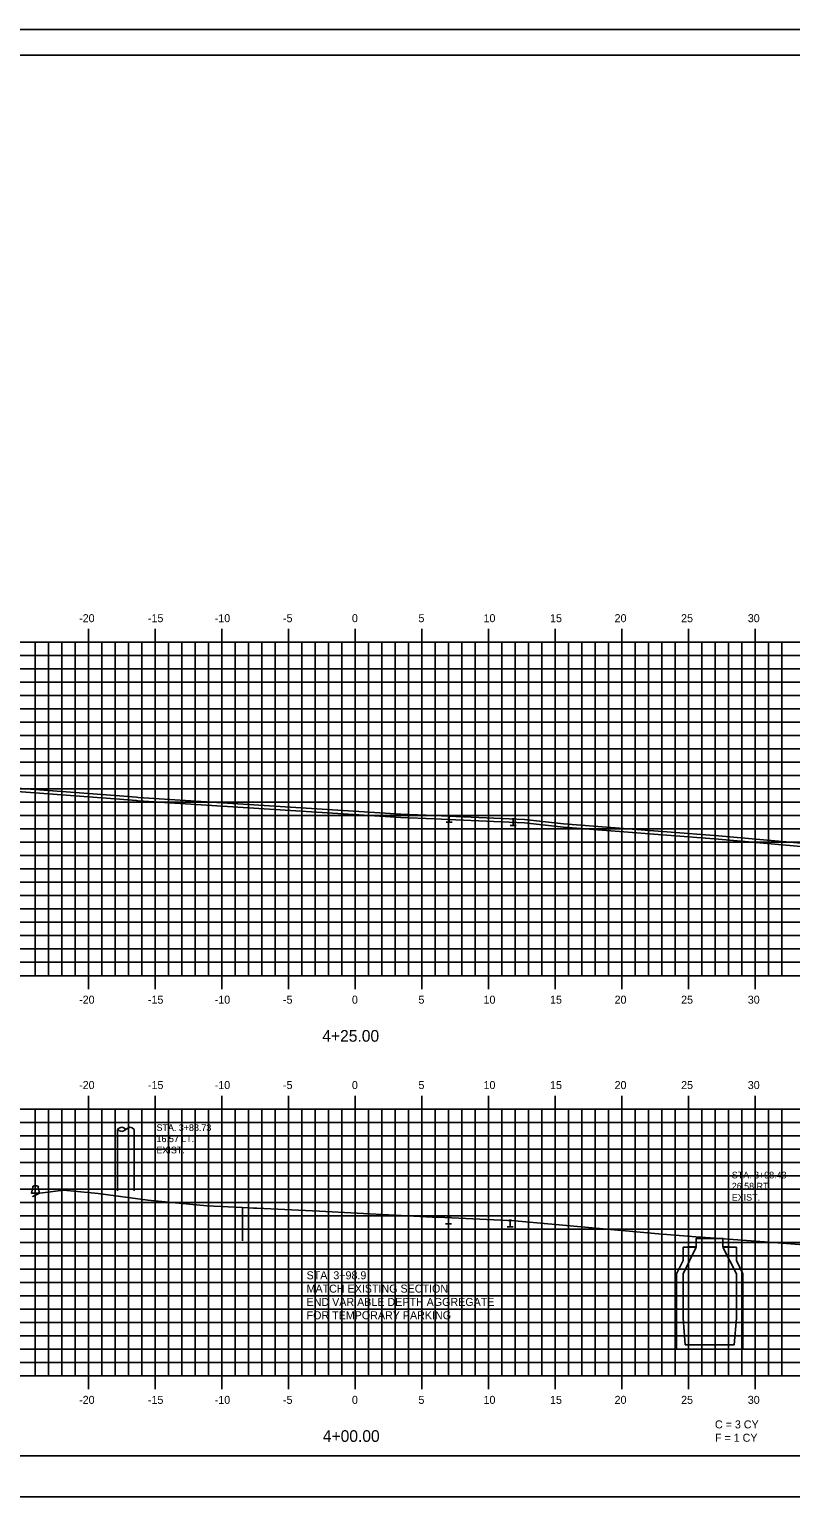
# Model space of a CAD drawing. Extents: x 1026213 to 1026383, y 394615 to 394725.
# Drawn here: x 1026272 to 1026329.1, y 394614.9 to 394724.9 of the extents above; entities that cross this region are included whole.
import ezdxf

# ---------------------------------------------------------------- set-up
doc = ezdxf.new("R2010")
doc.units = 0
for name, color, linetype in [('ANNOTATION', 7, 'Continuous'), ('BORDER', 7, 'Continuous'), ('D_Roadway_Centerline', 7, 'Continuous'), ('D_Roadway_SlopeLines', 7, 'Continuous'), ('D_Text_Monospaced', 7, 'Continuous'), ('H_V ANNOTATION', 7, 'Continuous'), ('MAJOR', 7, 'Continuous'), ('MINOR', 7, 'Continuous'), ('PLOT BOUNDARY', 7, 'Continuous'), ('S_Curb_Type_3', 7, 'Continuous'), ('S_Drainage_CB', 7, 'Continuous'), ('S_Railroad_Tracks', 7, 'Continuous'), ('S_Roadway_Centerline', 7, 'Continuous'), ('S_Roadway_Edge_Pavement', 7, 'Continuous'), ('S_Utilities_Pole_Power', 7, 'Continuous')]:
    doc.layers.add(name, color=color, linetype=linetype)

msp = doc.modelspace()

# ---------------------------------------------------------------- linework, layer by layer
at = {"layer": 'BORDER'}
for p, q in [((1026381.43, 394722.93), (1026221.43, 394722.93)), ((1026221.43, 394617.93), (1026381.43, 394617.93))]:
    msp.add_line(p, q, dxfattribs=at)
at = {"layer": 'D_Roadway_SlopeLines'}
msp.add_lwpolyline([(1026296.43, 394636.14), (1026296.43, 394636.14)], dxfattribs=at)
at = {"layer": 'MAJOR'}
for p, q in [((1026226.43, 394678.93), (1026366.43, 394678.93)), ((1026276.43, 394679.93), (1026276.43, 394678.93)), ((1026276.43, 394653.93), (1026276.43, 394678.93)), ((1026281.43, 394679.93), (1026281.43, 394678.93)), ((1026281.43, 394653.93), (1026281.43, 394678.93)), ((1026286.43, 394679.93), (1026286.43, 394678.93)), ((1026286.43, 394653.93), (1026286.43, 394678.93)), ((1026291.43, 394679.93), (1026291.43, 394678.93)), ((1026291.43, 394653.93), (1026291.43, 394678.93)), ((1026296.43, 394679.93), (1026296.43, 394678.93)), ((1026296.43, 394653.93), (1026296.43, 394678.93)), ((1026301.43, 394679.93), (1026301.43, 394678.93)), ((1026301.43, 394653.93), (1026301.43, 394678.93)), ((1026306.43, 394679.93), (1026306.43, 394678.93)), ((1026306.43, 394653.93), (1026306.43, 394678.93)), ((1026311.43, 394679.93), (1026311.43, 394678.93)), ((1026311.43, 394653.93), (1026311.43, 394678.93)), ((1026316.43, 394679.93), (1026316.43, 394678.93)), ((1026316.43, 394653.93), (1026316.43, 394678.93)), ((1026321.43, 394679.93), (1026321.43, 394678.93)), ((1026321.43, 394653.93), (1026321.43, 394678.93)), ((1026326.43, 394679.93), (1026326.43, 394678.93)), ((1026326.43, 394653.93), (1026326.43, 394678.93)), ((1026226.43, 394673.93), (1026366.43, 394673.93)), ((1026226.43, 394668.93), (1026366.43, 394668.93)), ((1026226.43, 394663.93), (1026366.43, 394663.93)), ((1026226.43, 394658.93), (1026366.43, 394658.93)), ((1026226.43, 394653.93), (1026366.43, 394653.93)), ((1026276.43, 394652.93), (1026276.43, 394653.93)), ((1026281.43, 394652.93), (1026281.43, 394653.93)), ((1026286.43, 394652.93), (1026286.43, 394653.93)), ((1026291.43, 394652.93), (1026291.43, 394653.93)), ((1026296.43, 394652.93), (1026296.43, 394653.93)), ((1026301.43, 394652.93), (1026301.43, 394653.93)), ((1026306.43, 394652.93), (1026306.43, 394653.93)), ((1026311.43, 394652.93), (1026311.43, 394653.93)), ((1026316.43, 394652.93), (1026316.43, 394653.93)), ((1026321.43, 394652.93), (1026321.43, 394653.93)), ((1026326.43, 394652.93), (1026326.43, 394653.93)), ((1026276.43, 394644.93), (1026276.43, 394643.93)), ((1026281.43, 394644.93), (1026281.43, 394643.93)), ((1026286.43, 394644.93), (1026286.43, 394643.93)), ((1026291.43, 394644.93), (1026291.43, 394643.93)), ((1026296.43, 394644.93), (1026296.43, 394643.93)), ((1026301.43, 394644.93), (1026301.43, 394643.93)), ((1026306.43, 394644.93), (1026306.43, 394643.93)), ((1026311.43, 394644.93), (1026311.43, 394643.93)), ((1026316.43, 394644.93), (1026316.43, 394643.93)), ((1026321.43, 394644.93), (1026321.43, 394643.93)), ((1026326.43, 394644.93), (1026326.43, 394643.93)), ((1026226.43, 394643.93), (1026366.43, 394643.93)), ((1026276.43, 394623.93), (1026276.43, 394643.93)), ((1026281.43, 394623.93), (1026281.43, 394643.93)), ((1026286.43, 394623.93), (1026286.43, 394643.93)), ((1026291.43, 394623.93), (1026291.43, 394643.93)), ((1026296.43, 394623.93), (1026296.43, 394643.93)), ((1026301.43, 394623.93), (1026301.43, 394643.93)), ((1026306.43, 394623.93), (1026306.43, 394643.93)), ((1026311.43, 394623.93), (1026311.43, 394643.93)), ((1026316.43, 394623.93), (1026316.43, 394643.93)), ((1026321.43, 394623.93), (1026321.43, 394643.93)), ((1026326.43, 394623.93), (1026326.43, 394643.93)), ((1026226.43, 394638.93), (1026366.43, 394638.93)), ((1026226.43, 394633.93), (1026366.43, 394633.93)), ((1026226.43, 394628.93), (1026366.43, 394628.93)), ((1026226.43, 394623.93), (1026366.43, 394623.93)), ((1026276.43, 394622.93), (1026276.43, 394623.93)), ((1026281.43, 394622.93), (1026281.43, 394623.93)), ((1026286.43, 394622.93), (1026286.43, 394623.93)), ((1026291.43, 394622.93), (1026291.43, 394623.93)), ((1026296.43, 394622.93), (1026296.43, 394623.93)), ((1026301.43, 394622.93), (1026301.43, 394623.93)), ((1026306.43, 394622.93), (1026306.43, 394623.93)), ((1026311.43, 394622.93), (1026311.43, 394623.93)), ((1026316.43, 394622.93), (1026316.43, 394623.93)), ((1026321.43, 394622.93), (1026321.43, 394623.93)), ((1026326.43, 394622.93), (1026326.43, 394623.93))]:
    msp.add_line(p, q, dxfattribs=at)
at = {"layer": 'MINOR'}
for p, q in [((1026272.43, 394653.93), (1026272.43, 394678.93)), ((1026273.43, 394653.93), (1026273.43, 394678.93)), ((1026274.43, 394653.93), (1026274.43, 394678.93)), ((1026275.43, 394653.93), (1026275.43, 394678.93)), ((1026277.43, 394653.93), (1026277.43, 394678.93)), ((1026278.43, 394653.93), (1026278.43, 394678.93)), ((1026279.43, 394653.93), (1026279.43, 394678.93)), ((1026280.43, 394653.93), (1026280.43, 394678.93)), ((1026282.43, 394653.93), (1026282.43, 394678.93)), ((1026283.43, 394653.93), (1026283.43, 394678.93)), ((1026284.43, 394653.93), (1026284.43, 394678.93)), ((1026285.43, 394653.93), (1026285.43, 394678.93)), ((1026287.43, 394653.93), (1026287.43, 394678.93)), ((1026288.43, 394653.93), (1026288.43, 394678.93)), ((1026289.43, 394653.93), (1026289.43, 394678.93)), ((1026290.43, 394653.93), (1026290.43, 394678.93)), ((1026292.43, 394653.93), (1026292.43, 394678.93)), ((1026293.43, 394653.93), (1026293.43, 394678.93)), ((1026294.43, 394653.93), (1026294.43, 394678.93)), ((1026295.43, 394653.93), (1026295.43, 394678.93)), ((1026297.43, 394653.93), (1026297.43, 394678.93)), ((1026298.43, 394653.93), (1026298.43, 394678.93)), ((1026299.43, 394653.93), (1026299.43, 394678.93)), ((1026300.43, 394653.93), (1026300.43, 394678.93)), ((1026302.43, 394653.93), (1026302.43, 394678.93)), ((1026303.43, 394653.93), (1026303.43, 394678.93)), ((1026304.43, 394653.93), (1026304.43, 394678.93)), ((1026305.43, 394653.93), (1026305.43, 394678.93)), ((1026307.43, 394653.93), (1026307.43, 394678.93)), ((1026308.43, 394653.93), (1026308.43, 394678.93)), ((1026309.43, 394653.93), (1026309.43, 394678.93)), ((1026310.43, 394653.93), (1026310.43, 394678.93)), ((1026312.43, 394653.93), (1026312.43, 394678.93)), ((1026313.43, 394653.93), (1026313.43, 394678.93)), ((1026314.43, 394653.93), (1026314.43, 394678.93)), ((1026315.43, 394653.93), (1026315.43, 394678.93)), ((1026317.43, 394653.93), (1026317.43, 394678.93)), ((1026318.43, 394653.93), (1026318.43, 394678.93)), ((1026319.43, 394653.93), (1026319.43, 394678.93)), ((1026320.43, 394653.93), (1026320.43, 394678.93)), ((1026322.43, 394653.93), (1026322.43, 394678.93)), ((1026323.43, 394653.93), (1026323.43, 394678.93)), ((1026324.43, 394653.93), (1026324.43, 394678.93)), ((1026325.43, 394653.93), (1026325.43, 394678.93)), ((1026327.43, 394653.93), (1026327.43, 394678.93)), ((1026328.43, 394653.93), (1026328.43, 394678.93)), ((1026226.43, 394677.93), (1026366.43, 394677.93)), ((1026226.43, 394676.93), (1026366.43, 394676.93)), ((1026226.43, 394675.93), (1026366.43, 394675.93)), ((1026226.43, 394674.93), (1026366.43, 394674.93)), ((1026226.43, 394672.93), (1026366.43, 394672.93)), ((1026226.43, 394671.93), (1026366.43, 394671.93)), ((1026226.43, 394670.93), (1026366.43, 394670.93)), ((1026226.43, 394669.93), (1026366.43, 394669.93)), ((1026226.43, 394667.93), (1026366.43, 394667.93)), ((1026226.43, 394666.93), (1026366.43, 394666.93)), ((1026226.43, 394665.93), (1026366.43, 394665.93)), ((1026226.43, 394664.93), (1026366.43, 394664.93)), ((1026226.43, 394662.93), (1026366.43, 394662.93)), ((1026226.43, 394661.93), (1026366.43, 394661.93)), ((1026226.43, 394660.93), (1026366.43, 394660.93)), ((1026226.43, 394659.93), (1026366.43, 394659.93)), ((1026226.43, 394657.93), (1026366.43, 394657.93)), ((1026226.43, 394656.93), (1026366.43, 394656.93)), ((1026226.43, 394655.93), (1026366.43, 394655.93)), ((1026226.43, 394654.93), (1026366.43, 394654.93)), ((1026272.43, 394623.93), (1026272.43, 394643.93)), ((1026273.43, 394623.93), (1026273.43, 394643.93)), ((1026274.43, 394623.93), (1026274.43, 394643.93)), ((1026275.43, 394623.93), (1026275.43, 394643.93)), ((1026277.43, 394623.93), (1026277.43, 394643.93)), ((1026278.43, 394623.93), (1026278.43, 394643.93)), ((1026279.43, 394623.93), (1026279.43, 394643.93)), ((1026280.43, 394623.93), (1026280.43, 394643.93)), ((1026282.43, 394623.93), (1026282.43, 394643.93)), ((1026283.43, 394623.93), (1026283.43, 394643.93)), ((1026284.43, 394623.93), (1026284.43, 394643.93)), ((1026285.43, 394623.93), (1026285.43, 394643.93)), ((1026287.43, 394623.93), (1026287.43, 394643.93)), ((1026288.43, 394623.93), (1026288.43, 394643.93)), ((1026289.43, 394623.93), (1026289.43, 394643.93)), ((1026290.43, 394623.93), (1026290.43, 394643.93)), ((1026292.43, 394623.93), (1026292.43, 394643.93)), ((1026293.43, 394623.93), (1026293.43, 394643.93)), ((1026294.43, 394623.93), (1026294.43, 394643.93)), ((1026295.43, 394623.93), (1026295.43, 394643.93)), ((1026297.43, 394623.93), (1026297.43, 394643.93)), ((1026298.43, 394623.93), (1026298.43, 394643.93)), ((1026299.43, 394623.93), (1026299.43, 394643.93)), ((1026300.43, 394623.93), (1026300.43, 394643.93)), ((1026302.43, 394623.93), (1026302.43, 394643.93)), ((1026303.43, 394623.93), (1026303.43, 394643.93)), ((1026304.43, 394623.93), (1026304.43, 394643.93)), ((1026305.43, 394623.93), (1026305.43, 394643.93)), ((1026307.43, 394623.93), (1026307.43, 394643.93)), ((1026308.43, 394623.93), (1026308.43, 394643.93)), ((1026309.43, 394623.93), (1026309.43, 394643.93)), ((1026310.43, 394623.93), (1026310.43, 394643.93)), ((1026312.43, 394623.93), (1026312.43, 394643.93)), ((1026313.43, 394623.93), (1026313.43, 394643.93)), ((1026314.43, 394623.93), (1026314.43, 394643.93)), ((1026315.43, 394623.93), (1026315.43, 394643.93)), ((1026317.43, 394623.93), (1026317.43, 394643.93)), ((1026318.43, 394623.93), (1026318.43, 394643.93)), ((1026319.43, 394623.93), (1026319.43, 394643.93)), ((1026320.43, 394623.93), (1026320.43, 394643.93)), ((1026322.43, 394623.93), (1026322.43, 394643.93)), ((1026323.43, 394623.93), (1026323.43, 394643.93)), ((1026324.43, 394623.93), (1026324.43, 394643.93)), ((1026325.43, 394623.93), (1026325.43, 394643.93)), ((1026327.43, 394623.93), (1026327.43, 394643.93)), ((1026328.43, 394623.93), (1026328.43, 394643.93)), ((1026226.43, 394642.93), (1026366.43, 394642.93)), ((1026226.43, 394641.93), (1026366.43, 394641.93)), ((1026226.43, 394640.93), (1026366.43, 394640.93)), ((1026226.43, 394639.93), (1026366.43, 394639.93)), ((1026226.43, 394637.93), (1026366.43, 394637.93)), ((1026226.43, 394636.93), (1026366.43, 394636.93)), ((1026226.43, 394635.93), (1026366.43, 394635.93)), ((1026226.43, 394634.93), (1026366.43, 394634.93)), ((1026226.43, 394632.93), (1026366.43, 394632.93)), ((1026226.43, 394631.93), (1026366.43, 394631.93)), ((1026226.43, 394630.93), (1026366.43, 394630.93)), ((1026226.43, 394629.93), (1026366.43, 394629.93)), ((1026226.43, 394627.93), (1026366.43, 394627.93)), ((1026226.43, 394626.93), (1026366.43, 394626.93)), ((1026226.43, 394625.93), (1026366.43, 394625.93)), ((1026226.43, 394624.93), (1026366.43, 394624.93))]:
    msp.add_line(p, q, dxfattribs=at)
at = {"layer": 'PLOT BOUNDARY'}
msp.add_lwpolyline([(1026213.34, 394614.87), (1026383.34, 394614.87), (1026383.34, 394724.87), (1026213.34, 394724.87)], close=True, dxfattribs=at)
at = {"layer": 'S_Curb_Type_3'}
for points in [[(1026272.25, 394638.07), (1026272.15, 394637.63), (1026272.77, 394637.63), (1026272.67, 394638.07)], [(1026272.25, 394638.07), (1026272.15, 394637.63), (1026272.77, 394637.63), (1026272.67, 394638.07)], [(1026272.55, 394638.17), (1026272.37, 394638.17)], [(1026272.55, 394638.17), (1026272.37, 394638.17)]]:
    msp.add_lwpolyline(points, dxfattribs=at)
for centre, start, end in [((1026272.37, 394638.04), 90, 167.0054), ((1026272.37, 394638.04), 90, 167.0054), ((1026272.55, 394638.04), 12.9946, 90), ((1026272.55, 394638.04), 12.9946, 90)]:
    msp.add_arc(centre, 0.125, start, end, dxfattribs=at)
at = {"layer": 'S_Drainage_CB'}
for p, q in [((1026322.01, 394633.57), (1026321.03, 394633.57)), ((1026321.03, 394633.57), (1026321.03, 394632.58)), ((1026321.03, 394631.57), (1026322.01, 394633.57)), ((1026322.01, 394633.57), (1026321.03, 394633.57)), ((1026321.03, 394633.57), (1026321.03, 394632.58)), ((1026321.03, 394631.57), (1026322.01, 394633.57)), ((1026325.03, 394633.57), (1026324.02, 394633.57)), ((1026324.02, 394633.57), (1026325.03, 394631.57)), ((1026325.03, 394633.57), (1026324.02, 394633.57)), ((1026324.02, 394633.57), (1026325.03, 394631.57)), ((1026325.03, 394632.58), (1026325.03, 394633.57)), ((1026325.03, 394632.58), (1026325.03, 394633.57)), ((1026321.03, 394632.58), (1026320.54, 394631.57)), ((1026321.03, 394632.58), (1026320.54, 394631.57)), ((1026325.52, 394631.57), (1026325.03, 394632.58)), ((1026325.52, 394631.57), (1026325.03, 394632.58)), ((1026320.54, 394631.57), (1026320.54, 394625.92)), ((1026320.54, 394631.57), (1026320.54, 394625.92)), ((1026321.03, 394628.25), (1026321.03, 394631.57)), ((1026321.03, 394628.25), (1026321.03, 394631.57)), ((1026325.03, 394631.57), (1026325.03, 394628.25)), ((1026325.03, 394631.57), (1026325.03, 394628.25)), ((1026325.52, 394625.92), (1026325.52, 394631.57)), ((1026325.52, 394625.92), (1026325.52, 394631.57)), ((1026321.19, 394626.25), (1026321.03, 394628.25)), ((1026321.19, 394626.25), (1026321.03, 394628.25)), ((1026325.03, 394628.25), (1026324.87, 394626.25)), ((1026325.03, 394628.25), (1026324.87, 394626.25)), ((1026324.87, 394626.25), (1026321.19, 394626.25)), ((1026324.87, 394626.25), (1026321.19, 394626.25)), ((1026320.54, 394625.92), (1026325.52, 394625.92)), ((1026320.54, 394625.92), (1026325.52, 394625.92))]:
    msp.add_line(p, q, dxfattribs=at)
msp.add_lwpolyline([(1026324.51, 394633.61), (1026324.02, 394633.61), (1026324.02, 394634.23), (1026322.01, 394634.23), (1026322.01, 394633.61), (1026321.52, 394633.61)], dxfattribs=at)
msp.add_lwpolyline([(1026324.51, 394633.61), (1026324.02, 394633.61), (1026324.02, 394634.23), (1026322.01, 394634.23), (1026322.01, 394633.61), (1026321.52, 394633.61)], dxfattribs=at)
at = {"layer": 'S_Railroad_Tracks'}
for p, q in [((1026303.37, 394665.93), (1026303.6, 394665.93)), ((1026303.37, 394665.93), (1026303.6, 394665.93)), ((1026303.48, 394665.93), (1026303.48, 394665.43)), ((1026303.48, 394665.93), (1026303.48, 394665.43)), ((1026303.25, 394665.43), (1026303.71, 394665.43)), ((1026303.25, 394665.43), (1026303.71, 394665.43)), ((1026308.06, 394665.2), (1026308.52, 394665.2)), ((1026308.06, 394665.2), (1026308.52, 394665.2)), ((1026308.18, 394665.7), (1026308.41, 394665.7)), ((1026308.18, 394665.7), (1026308.41, 394665.7)), ((1026308.29, 394665.7), (1026308.29, 394665.2)), ((1026308.29, 394665.7), (1026308.29, 394665.2)), ((1026303.2, 394635.33), (1026303.66, 394635.33)), ((1026303.21, 394635.33), (1026303.66, 394635.33)), ((1026303.32, 394635.83), (1026303.55, 394635.83)), ((1026303.32, 394635.83), (1026303.55, 394635.83)), ((1026303.43, 394635.83), (1026303.43, 394635.33)), ((1026303.43, 394635.83), (1026303.43, 394635.33)), ((1026307.83, 394635.1), (1026308.29, 394635.1)), ((1026307.83, 394635.1), (1026308.29, 394635.1)), ((1026307.95, 394635.6), (1026308.17, 394635.6)), ((1026307.95, 394635.6), (1026308.17, 394635.6)), ((1026308.06, 394635.6), (1026308.06, 394635.1)), ((1026308.06, 394635.6), (1026308.06, 394635.1))]:
    msp.add_line(p, q, dxfattribs=at)
at = {"layer": 'S_Roadway_Centerline'}
for points in [[(1026256.36, 394669.08), (1026256.36, 394669.08), (1026258.36, 394668.94), (1026278.77, 394667.41), (1026280.04, 394667.3), (1026280.16, 394667.29), (1026299.85, 394666.05), (1026302.39, 394665.94), (1026303.98, 394665.86), (1026303.98, 394665.86), (1026303.98, 394665.86), (1026309.14, 394665.64), (1026309.14, 394665.64), (1026312.05, 394665.32), (1026323.69, 394664.41), (1026333.54, 394663.54), (1026333.54, 394663.54), (1026333.55, 394663.54), (1026346.49, 394662.46), (1026346.49, 394662.46), (1026363.44, 394661.04), (1026365.47, 394660.9), (1026365.47, 394660.9), (1026366.43, 394660.82)], [(1026256.36, 394668.83), (1026256.36, 394668.83), (1026258.36, 394668.69), (1026278.77, 394667.16), (1026280.04, 394667.05), (1026280.16, 394667.04), (1026299.85, 394665.8), (1026302.39, 394665.69), (1026303.98, 394665.61), (1026303.98, 394665.61), (1026303.98, 394665.61), (1026309.14, 394665.39), (1026309.14, 394665.39), (1026312.05, 394665.07), (1026323.69, 394664.16), (1026333.54, 394663.29), (1026333.54, 394663.29), (1026333.55, 394663.29), (1026346.49, 394662.21), (1026346.49, 394662.21), (1026363.44, 394660.79), (1026365.47, 394660.65), (1026365.47, 394660.65), (1026366.43, 394660.57)], [(1026272.24, 394637.36), (1026272.26, 394637.38), (1026272.77, 394637.63), (1026272.98, 394637.66), (1026274.56, 394637.86), (1026274.56, 394637.86), (1026277.15, 394637.6), (1026280.88, 394637.1), (1026285.31, 394636.68), (1026287.98, 394636.56), (1026287.98, 394636.56), (1026287.98, 394636.56), (1026288.81, 394636.51), (1026289.06, 394636.5), (1026289.06, 394636.5), (1026293.76, 394636.28), (1026302.23, 394635.83), (1026302.63, 394635.82), (1026308.41, 394635.55), (1026308.41, 394635.55), (1026319.19, 394634.58), (1026321.98, 394634.34), (1026323.45, 394634.24), (1026323.45, 394634.24), (1026328.45, 394633.87), (1026365.64, 394631.01)]]:
    msp.add_lwpolyline(points, dxfattribs=at)
at = {"layer": 'S_Roadway_Edge_Pavement'}
msp.add_line((1026287.98, 394636.56), (1026287.98, 394634.06), dxfattribs=at)
msp.add_line((1026287.98, 394636.56), (1026287.98, 394634.06), dxfattribs=at)
at = {"layer": 'S_Utilities_Pole_Power'}
for p, q in [((1026278.62, 394642.41), (1026278.77, 394642.52)), ((1026278.62, 394642.41), (1026278.77, 394642.52)), ((1026278.62, 394637.79), (1026278.62, 394642.41)), ((1026278.77, 394642.3), (1026278.62, 394642.41)), ((1026278.62, 394637.79), (1026278.62, 394642.41)), ((1026278.77, 394642.3), (1026278.62, 394642.41)), ((1026279.09, 394642.52), (1026279.24, 394642.41)), ((1026279.09, 394642.52), (1026279.24, 394642.41)), ((1026279.24, 394642.41), (1026279.09, 394642.3)), ((1026279.24, 394642.41), (1026279.09, 394642.3)), ((1026279.4, 394642.52), (1026279.24, 394642.41)), ((1026279.4, 394642.52), (1026279.24, 394642.41)), ((1026279.87, 394642.41), (1026279.71, 394642.52)), ((1026279.87, 394642.41), (1026279.71, 394642.52)), ((1026279.87, 394637.79), (1026279.87, 394642.41)), ((1026279.87, 394637.79), (1026279.87, 394642.41))]:
    msp.add_line(p, q, dxfattribs=at)
for centre, start, end in [((1026278.93, 394642.3), 90, 125.2644), ((1026278.93, 394642.3), 90, 125.2644), ((1026278.93, 394642.52), 234.7356, 270), ((1026278.93, 394642.52), 234.7356, 270), ((1026278.93, 394642.3), 54.7356, 90), ((1026278.93, 394642.3), 54.7356, 90), ((1026278.93, 394642.52), 270, 305.2644), ((1026278.93, 394642.52), 270, 305.2644), ((1026279.56, 394642.3), 90, 125.2644), ((1026279.56, 394642.3), 90, 125.2644), ((1026279.56, 394642.3), 54.7356, 90), ((1026279.56, 394642.3), 54.7356, 90)]:
    msp.add_arc(centre, 0.271, start, end, dxfattribs=at)

# ---------------------------------------------------------------- texts
at = {"layer": 'ANNOTATION'}
for s, p in [('STA. 3+98.9', (1026292.79, 394631.17)), ('MATCH EXISTING SECTION', (1026292.79, 394630.17)), ('END VARIABLE DEPTH AGGREGATE', (1026292.79, 394629.17)), ('FOR TEMPORARY PARKING', (1026292.79, 394628.17)), ('C = 3 CY', (1026323.42, 394619.99)), ('F = 1 CY', (1026323.42, 394618.99))]:
    msp.add_text(s, height=0.6, dxfattribs=at).set_placement(p)
at = {"layer": 'D_Roadway_Centerline'}
for s, p in [('C', (1026296.43, 394636.14)), ('L', (1026296.43, 394636.13))]:
    msp.add_text(s, height=0.0146, dxfattribs=at).set_placement(p)
at = {"layer": 'D_Text_Monospaced'}
for s, p in [('STA. 3+88.73', (1026281.53, 394642.29)), ('STA. 3+88.73', (1026281.54, 394642.29)), ('16.57 LT.', (1026281.53, 394641.45)), ('16.57 LT.', (1026281.54, 394641.45)), ('EXIST. ', (1026281.53, 394640.61)), ('EXIST. ', (1026281.54, 394640.61)), ('STA. 3+98.43', (1026324.68, 394638.73)), ('STA. 3+98.43', (1026324.68, 394638.73)), ('26.58 RT.', (1026324.68, 394637.9)), ('26.58 RT.', (1026324.68, 394637.9)), ('EXIST. ', (1026324.68, 394637.06)), ('EXIST. ', (1026324.68, 394637.06))]:
    msp.add_text(s, height=0.5, dxfattribs=at).set_placement(p)
at = {"layer": 'H_V ANNOTATION'}
for s, height, p in [('-20', 0.6, (1026275.73, 394680.43)), ('-15', 0.6, (1026280.89, 394680.43)), ('-10', 0.6, (1026285.9, 394680.43)), ('-5', 0.6, (1026291.02, 394680.43)), ('0', 0.6, (1026296.19, 394680.43)), ('5', 0.6, (1026301.18, 394680.43)), ('10', 0.6, (1026306.06, 394680.43)), ('15', 0.6, (1026311.05, 394680.43)), ('20', 0.6, (1026315.89, 394680.43)), ('25', 0.6, (1026320.88, 394680.43)), ('30', 0.6, (1026325.88, 394680.43)), ('-20', 0.6, (1026275.73, 394651.83)), ('-15', 0.6, (1026280.89, 394651.83)), ('-10', 0.6, (1026285.9, 394651.83)), ('-5', 0.6, (1026291.02, 394651.83)), ('0', 0.6, (1026296.19, 394651.83)), ('5', 0.6, (1026301.18, 394651.83)), ('10', 0.6, (1026306.06, 394651.83)), ('15', 0.6, (1026311.05, 394651.83)), ('20', 0.6, (1026315.89, 394651.83)), ('25', 0.6, (1026320.88, 394651.83)), ('30', 0.6, (1026325.88, 394651.83)), ('4+25.00', 0.875, (1026293.97, 394648.98)), ('-20', 0.6, (1026275.73, 394645.43)), ('-15', 0.6, (1026280.89, 394645.43)), ('-10', 0.6, (1026285.9, 394645.43)), ('-5', 0.6, (1026291.02, 394645.43)), ('0', 0.6, (1026296.19, 394645.43)), ('5', 0.6, (1026301.18, 394645.43)), ('10', 0.6, (1026306.06, 394645.43)), ('15', 0.6, (1026311.05, 394645.43)), ('20', 0.6, (1026315.89, 394645.43)), ('25', 0.6, (1026320.88, 394645.43)), ('30', 0.6, (1026325.88, 394645.43)), ('-20', 0.6, (1026275.73, 394621.83)), ('-15', 0.6, (1026280.89, 394621.83)), ('-10', 0.6, (1026285.9, 394621.83)), ('-5', 0.6, (1026291.02, 394621.83)), ('0', 0.6, (1026296.19, 394621.83)), ('5', 0.6, (1026301.18, 394621.83)), ('10', 0.6, (1026306.06, 394621.83)), ('15', 0.6, (1026311.05, 394621.83)), ('20', 0.6, (1026315.89, 394621.83)), ('25', 0.6, (1026320.88, 394621.83)), ('30', 0.6, (1026325.88, 394621.83)), ('4+00.00', 0.875, (1026294.01, 394618.98))]:
    msp.add_text(s, height=height, dxfattribs=at).set_placement(p)
at = {"layer": 'S_Roadway_Centerline'}
for s, p in [('C', (1026278.76, 394667.41)), ('C', (1026278.76, 394667.41)), ('L', (1026278.76, 394667.4)), ('L', (1026278.76, 394667.4)), ('C', (1026278.76, 394667.16)), ('C', (1026278.76, 394667.16)), ('L', (1026278.76, 394667.15)), ('L', (1026278.76, 394667.15))]:
    msp.add_text(s, height=0.0146, dxfattribs=at).set_placement(p)

doc.saveas('drawing.dxf')
